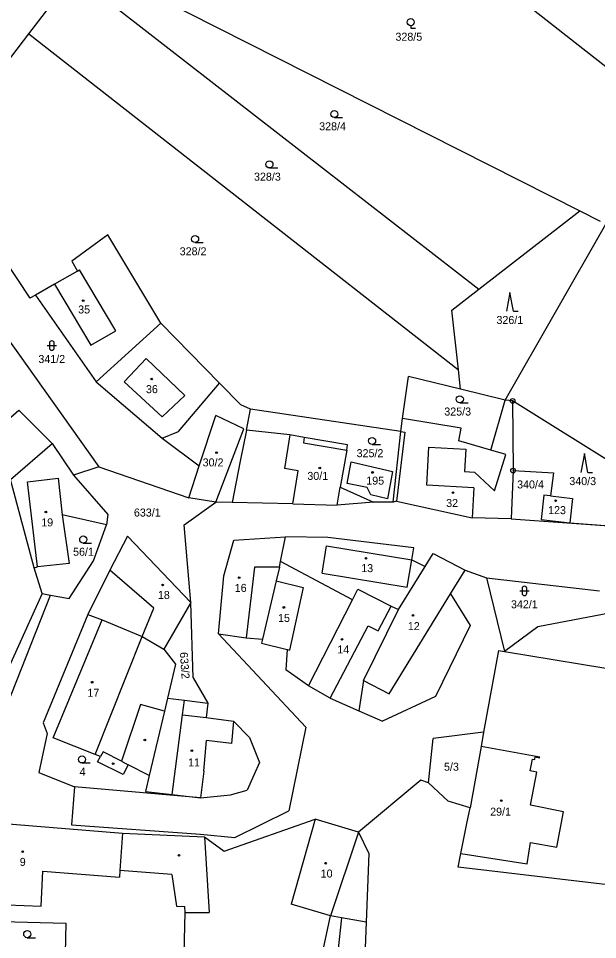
# Model space of a CAD drawing. Extents: x -654459 to -653618, y -1151040 to -1150446.
# Drawn here: x -654025.1 to -653902.1, y -1150881.9 to -1150686.2 of the extents above; entities that cross this region are included whole.
import ezdxf

# ---------------------------------------------------------------- set-up
doc = ezdxf.new("R2010")
doc.units = 0
for name, color, linetype in [('Vrstva 1', 7, 'Continuous'), ('Vrstva 13', 7, 'Continuous'), ('Vrstva 2', 7, 'Continuous'), ('Vrstva 3', 7, 'Continuous'), ('Vrstva 4', 7, 'Continuous'), ('Vrstva 5', 7, 'Continuous'), ('Vrstva 8', 7, 'Continuous')]:
    doc.layers.add(name, color=color, linetype=linetype)

msp = doc.modelspace()

# ---------------------------------------------------------------- linework, layer by layer
at = {"layer": 'Vrstva 1'}
for points in [[(-653968.37, -1150643), (-653888.85, -1150705.43)], [(-654012.68, -1150677.36), (-653927.29, -1150743.71)], [(-654002.02, -1150678.37), (-653905.88, -1150727.07)], [(-654022.86, -1150689.48), (-654015.09, -1150679.29)], [(-654028.99, -1150697.51), (-654022.86, -1150689.48)], [(-654022.86, -1150689.48), (-653931.64, -1150760.87)], [(-654039.87, -1150719.69), (-654022.63, -1150745.66)], [(-653927.29, -1150743.71), (-653905.88, -1150727.07)], [(-653905.88, -1150727.07), (-653901.55, -1150729.27)], [(-653921.68, -1150767.33), (-653900.29, -1150729.91)], [(-654043.19, -1150732.01), (-654008, -1150781.45)], [(-654006.05, -1150732.21), (-654013.73, -1150737.79)], [(-653994.84, -1150750.97), (-654006.05, -1150732.21)], [(-654013.73, -1150737.79), (-654012.53, -1150739.89)], [(-654012.53, -1150739.89), (-654017.42, -1150742.69)], [(-654017.42, -1150742.69), (-654021.44, -1150744.99)], [(-654021.44, -1150744.99), (-654022.63, -1150745.66)], [(-654021.44, -1150744.99), (-654008.57, -1150763.42)], [(-653933.02, -1150748.16), (-653927.29, -1150743.71)], [(-653931.64, -1150760.87), (-653933.02, -1150748.16)], [(-653994.84, -1150750.97), (-654008.57, -1150763.42)], [(-653994.84, -1150750.97), (-653982.37, -1150763.68)], [(-653931.19, -1150764.98), (-653931.64, -1150760.87)], [(-653943.5, -1150771.19), (-653942.2, -1150762.25)], [(-653931.19, -1150764.98), (-653942.2, -1150762.25)], [(-654008.57, -1150763.42), (-653994.51, -1150775.36)], [(-653991.07, -1150773.99), (-653982.37, -1150763.68)], [(-653977.82, -1150768.32), (-653982.37, -1150763.68)], [(-653921.68, -1150767.33), (-653931.19, -1150764.98)], [(-653975.75, -1150769.21), (-653977.82, -1150768.32)], [(-653924.72, -1150777.93), (-653921.68, -1150767.33)], [(-653920.11, -1150767.47), (-653921.68, -1150767.33)], [(-653920.11, -1150767.47), (-653920.01, -1150782.27)], [(-653897.16, -1150781.78), (-653920.11, -1150767.47)], [(-654030.11, -1150773.82), (-654024.99, -1150769.41)], [(-654024.99, -1150769.41), (-654017.92, -1150776.47)], [(-653976.64, -1150773.7), (-653975.75, -1150769.21)], [(-653943.83, -1150773.98), (-653975.75, -1150769.21)], [(-653943.83, -1150773.98), (-653943.5, -1150771.19)], [(-653931.04, -1150773.25), (-653943.5, -1150771.19)], [(-653994.51, -1150775.36), (-653991.07, -1150773.99)], [(-653976.64, -1150773.7), (-653977.95, -1150780.23)], [(-653967.44, -1150774.67), (-653976.64, -1150773.7)], [(-653945.49, -1150788.94), (-653943.83, -1150773.98)], [(-653931.57, -1150775.97), (-653931.04, -1150773.25)], [(-654017.92, -1150776.47), (-654013.38, -1150783.24)], [(-653994.51, -1150775.36), (-653986.65, -1150781.24)], [(-653964.37, -1150775.2), (-653967.44, -1150774.67)], [(-653955.16, -1150776.79), (-653964.37, -1150775.2)], [(-653924.72, -1150777.93), (-653931.57, -1150775.97)], [(-653955.36, -1150777.94), (-653956.75, -1150785.81)], [(-653955.36, -1150777.94), (-653955.16, -1150776.79)], [(-653977.95, -1150780.23), (-653979.71, -1150789.03)], [(-653955.22, -1150785.01), (-653954.42, -1150780.37)], [(-653954.42, -1150780.37), (-653945.61, -1150782.45)], [(-654008, -1150781.45), (-654013.38, -1150783.24)], [(-654008, -1150781.45), (-653988.88, -1150788.06)], [(-653988.88, -1150788.06), (-653986.65, -1150781.24)], [(-653920.01, -1150782.27), (-653920.44, -1150792.48)], [(-653920.01, -1150782.27), (-653911.44, -1150782.73)], [(-654021.7, -1150802.89), (-654026.75, -1150784.17)], [(-654013.38, -1150783.24), (-654006.09, -1150791.56)], [(-653945.61, -1150782.45), (-653946.72, -1150788.28)], [(-653911.44, -1150782.73), (-653912.05, -1150787.64)], [(-653956.75, -1150785.81), (-653949.63, -1150788.96)], [(-653951.03, -1150785.84), (-653955.22, -1150785.01)], [(-653950.24, -1150787.42), (-653951.03, -1150785.84)], [(-653983.13, -1150788.95), (-653988.88, -1150788.06)], [(-653946.72, -1150788.28), (-653950.24, -1150787.42)], [(-653913.46, -1150787.47), (-653914.09, -1150792.62)], [(-653912.05, -1150787.64), (-653913.46, -1150787.47)], [(-653912.05, -1150787.64), (-653907.38, -1150788.2)], [(-653907.38, -1150788.2), (-653907.99, -1150793.34)], [(-653989.9, -1150793.76), (-653983.13, -1150788.95)], [(-653979.71, -1150789.03), (-653983.13, -1150788.95)], [(-653966.77, -1150789.35), (-653979.71, -1150789.03)], [(-653966.77, -1150789.35), (-653957.41, -1150789.58)], [(-653949.63, -1150788.96), (-653957.41, -1150789.58)], [(-653945.49, -1150788.94), (-653949.63, -1150788.96)], [(-653944.79, -1150788.76), (-653945.49, -1150788.94)], [(-653944.79, -1150788.76), (-653928.72, -1150792.32)], [(-654015.79, -1150791.67), (-654014.26, -1150801.98)], [(-654006.36, -1150793.78), (-654015.79, -1150791.67)], [(-654006.09, -1150791.56), (-654006.36, -1150793.78)], [(-654009.12, -1150801.45), (-654006.36, -1150793.78)], [(-653988.45, -1150810.25), (-653989.9, -1150793.76)], [(-653920.44, -1150792.48), (-653928.72, -1150792.32)], [(-653920.44, -1150792.48), (-653896.64, -1150794.22)], [(-653914.09, -1150792.62), (-653907.99, -1150793.34)], [(-653907.99, -1150793.34), (-653896.64, -1150794.22)], [(-654001.87, -1150796.2), (-654005.65, -1150803.38)], [(-654001.87, -1150796.2), (-653988.45, -1150810.25)], [(-653981.47, -1150804.63), (-653979.32, -1150797.04)], [(-653979.32, -1150797.04), (-653968.38, -1150796.31)], [(-653969.41, -1150801.57), (-653968.38, -1150796.31)], [(-653959.35, -1150796.5), (-653968.38, -1150796.31)], [(-653941.12, -1150798.68), (-653959.35, -1150796.5)], [(-653941.54, -1150801.2), (-653941.12, -1150798.68)], [(-653938.7, -1150802.62), (-653937.02, -1150799.89)], [(-653937.02, -1150799.89), (-653930.19, -1150803.4)], [(-654014.26, -1150801.98), (-654021.01, -1150802.74)], [(-654014.26, -1150809.42), (-654009.12, -1150801.45)], [(-653969.64, -1150802.75), (-653969.41, -1150801.57)], [(-653954.1, -1150809.68), (-653969.41, -1150801.57)], [(-653941.54, -1150801.2), (-653938.7, -1150802.62)], [(-654021.7, -1150802.89), (-654021.01, -1150802.74)], [(-654020.03, -1150808.4), (-654021.7, -1150802.89)], [(-654005.65, -1150803.38), (-654010.3, -1150812.82)], [(-653969.64, -1150802.75), (-653970.33, -1150805.68)], [(-653944.35, -1150811.8), (-653938.7, -1150802.62)], [(-653933.29, -1150808.44), (-653930.19, -1150803.4)], [(-653930.19, -1150803.4), (-653925.66, -1150805.07)], [(-653982.57, -1150816.95), (-653981.47, -1150804.63)], [(-653970.33, -1150805.68), (-653973.24, -1150818.04)], [(-653925.66, -1150805.07), (-653921.83, -1150820.7)], [(-653925.66, -1150805.07), (-653901.67, -1150807.82)], [(-653954.1, -1150809.68), (-653952.98, -1150807.48)], [(-653952.98, -1150807.48), (-653945.88, -1150811.03)], [(-654027.56, -1150832.2), (-654018.25, -1150808.73)], [(-654020.03, -1150808.4), (-654027.41, -1150824.64)], [(-654020.03, -1150808.4), (-654018.25, -1150808.73)], [(-654018.25, -1150808.73), (-654014.26, -1150809.42)], [(-653963.48, -1150828.02), (-653954.1, -1150809.68)], [(-653933.29, -1150808.44), (-653929.12, -1150815.14)], [(-653879.89, -1150808.79), (-653914.75, -1150815.43)], [(-653988.45, -1150810.25), (-653994.2, -1150820.22)], [(-653987.95, -1150826.27), (-653988.45, -1150810.25)], [(-653945.88, -1150811.03), (-653944.35, -1150811.8)], [(-654010.3, -1150812.82), (-654019.83, -1150835.82)], [(-654010.3, -1150812.82), (-654007.27, -1150813.93)], [(-653951.82, -1150826.83), (-653944.35, -1150811.8)], [(-654017.66, -1150839.04), (-654007.27, -1150813.93)], [(-654007.27, -1150813.93), (-653998.8, -1150817.5)], [(-653929.12, -1150815.14), (-653936.51, -1150830.25)], [(-653914.75, -1150815.43), (-653921.83, -1150820.7)], [(-653998.8, -1150817.5), (-653994.2, -1150820.22)], [(-653982.57, -1150816.95), (-653964.04, -1150836.77)], [(-653982.57, -1150816.95), (-653976.7, -1150817.82)], [(-653976.7, -1150817.82), (-653973.24, -1150818.04)], [(-653973.24, -1150818.04), (-653973.45, -1150818.92)], [(-653973.45, -1150818.92), (-653968, -1150820.26)], [(-653994.2, -1150820.22), (-653991.71, -1150823.35)], [(-653968, -1150820.26), (-653968.27, -1150824.57)], [(-653923.12, -1150820.49), (-653926.31, -1150837.82)], [(-653923.12, -1150820.49), (-653921.83, -1150820.7)], [(-653921.83, -1150820.7), (-653895.17, -1150825.09)], [(-653991.71, -1150823.35), (-653993.41, -1150830.6)], [(-653963.48, -1150828.02), (-653968.27, -1150824.57)], [(-653987.95, -1150826.27), (-653984.85, -1150831.66)], [(-653951.82, -1150826.83), (-653952.77, -1150833.27)], [(-653958.83, -1150830.58), (-653963.48, -1150828.02)], [(-653993.41, -1150830.6), (-653994.05, -1150833.34)], [(-653993.41, -1150830.6), (-653989.83, -1150831.04)], [(-653989.83, -1150831.04), (-653984.85, -1150831.66)], [(-653958.83, -1150830.58), (-653952.77, -1150833.27)], [(-653936.51, -1150830.25), (-653947.77, -1150835.5)], [(-653984.85, -1150831.66), (-653985.2, -1150834.68)], [(-653952.77, -1150833.27), (-653947.77, -1150835.5)], [(-653994.05, -1150833.34), (-653997.27, -1150847.01)], [(-653985.2, -1150834.68), (-653979.39, -1150835.48)], [(-654019.83, -1150835.82), (-654018.93, -1150838.08)], [(-653979.39, -1150835.48), (-653975.96, -1150838.93)], [(-653964.04, -1150836.77), (-653967.66, -1150854.52)], [(-654018.93, -1150838.08), (-654020.7, -1150846.4)], [(-654008.75, -1150842.55), (-654017.66, -1150839.04)], [(-653975.96, -1150838.93), (-653973.87, -1150844.24)], [(-653937.98, -1150848.62), (-653936.97, -1150839.17)], [(-653926.31, -1150837.82), (-653936.97, -1150839.17)], [(-653926.31, -1150837.82), (-653926.8, -1150840.86)], [(-653931.11, -1150863.57), (-653917.05, -1150865.8), (-653916.33, -1150861.24), (-653910.76, -1150862.28), (-653909.31, -1150854.72), (-653916.33, -1150853.37), (-653914.96, -1150846.3), (-653916.39, -1150846.02), (-653915.92, -1150843.57), (-653915.42, -1150843.66), (-653915.31, -1150843.07), (-653914.38, -1150843.25), (-653914.35, -1150843.11), (-653926.8, -1150840.86)], [(-653926.8, -1150840.86), (-653929.15, -1150853.89)], [(-654007.63, -1150842.99), (-654008.75, -1150842.55)], [(-654008.24, -1150844.1), (-654007.63, -1150842.99)], [(-654002.79, -1150846.83), (-654008.24, -1150844.1)], [(-654001.75, -1150844.76), (-654002.79, -1150846.83)], [(-653997.27, -1150847.01), (-654001.75, -1150844.76)], [(-653973.87, -1150844.24), (-653975.07, -1150846.96)], [(-654020.7, -1150846.4), (-654013.17, -1150849.43)], [(-653997.27, -1150847.01), (-653998.07, -1150850.41)], [(-653975.07, -1150846.96), (-653976.47, -1150850.13)], [(-653939.58, -1150848.05), (-653952.85, -1150859.1)], [(-653937.98, -1150848.62), (-653939.58, -1150848.05)], [(-653933.78, -1150852.52), (-653937.98, -1150848.62)], [(-654013.17, -1150849.43), (-654013.81, -1150857.53)], [(-653986.41, -1150851.81), (-654013.17, -1150849.43)], [(-653998.07, -1150850.41), (-653992.43, -1150851.08)], [(-653980, -1150851.16), (-653976.47, -1150850.13)], [(-653992.43, -1150851.08), (-653986.41, -1150851.81)], [(-653986.41, -1150851.81), (-653980, -1150851.16)], [(-653929.15, -1150853.89), (-653933.78, -1150852.52)], [(-653979.12, -1150860.22), (-653967.66, -1150854.52)], [(-653929.82, -1150857.2), (-653929.15, -1150853.89)], [(-653981.39, -1150863.1), (-653962.07, -1150856.32)], [(-653952.85, -1150859.1), (-653962.07, -1150856.32)], [(-654029.83, -1150857.12), (-654002.97, -1150859.28)], [(-654013.81, -1150857.53), (-653986.42, -1150859.51)], [(-653931.11, -1150863.57), (-653929.82, -1150857.2)], [(-654002.97, -1150859.28), (-653985.52, -1150860.06)], [(-653986.42, -1150859.51), (-653979.12, -1150860.22)], [(-653985.52, -1150860.06), (-653981.39, -1150863.1)], [(-653985.52, -1150860.06), (-653984.54, -1150876.12)], [(-653952.85, -1150859.1), (-653950.63, -1150863.63)], [(-653950.63, -1150863.63), (-653951.19, -1150878.22)], [(-653931.71, -1150866.51), (-653931.11, -1150863.57)], [(-653879.52, -1150872.65), (-653931.71, -1150866.51)], [(-653989.92, -1150887.76), (-653989.66, -1150876.12)], [(-653989.66, -1150876.12), (-653984.54, -1150876.12)], [(-654031.34, -1150877.98), (-654015, -1150878.38)], [(-653960.43, -1150884.41), (-653958.81, -1150876.82)], [(-653956.45, -1150877.25), (-653958.81, -1150876.82)], [(-653951.19, -1150878.22), (-653956.45, -1150877.25)], [(-653951.19, -1150878.22), (-653951.68, -1150890.98)], [(-654015, -1150878.38), (-654015.19, -1150887.93)]]:
    msp.add_lwpolyline(points, dxfattribs=at)
at = {"layer": 'Vrstva 3'}
for p, q in [((-653941.76, -1150687.74), (-653941.76, -1150688.24)), ((-653941.76, -1150688.24), (-653940.76, -1150688.24)), ((-653957.99, -1150707.27), (-653956.24, -1150707.27)), ((-653971.76, -1150717.97), (-653970.01, -1150717.97)), ((-653987.55, -1150733.82), (-653985.8, -1150733.82)), ((-653920.69, -1150744.41), (-653921.44, -1150748.41)), ((-653919.94, -1150748.41), (-653920.69, -1150744.41)), ((-653919.94, -1150748.41), (-653918.94, -1150748.41)), ((-654018.97, -1150755.7), (-654016.97, -1150755.7)), ((-654018.47, -1150755.2), (-654018.47, -1150756.2)), ((-654017.47, -1150756.2), (-654017.47, -1150755.2)), ((-653931.33, -1150767.86), (-653929.58, -1150767.86)), ((-653949.96, -1150776.71), (-653948.21, -1150776.71)), ((-653904.87, -1150778.64), (-653905.62, -1150782.64)), ((-653904.12, -1150782.64), (-653904.87, -1150778.64)), ((-653904.12, -1150782.64), (-653903.12, -1150782.64)), ((-654011.3, -1150797.65), (-654009.55, -1150797.65)), ((-653918.61, -1150807.81), (-653916.61, -1150807.81)), ((-653918.11, -1150807.31), (-653918.11, -1150808.31)), ((-653917.11, -1150808.31), (-653917.11, -1150807.31)), ((-654011.56, -1150844.37), (-654009.81, -1150844.37)), ((-654023.2, -1150881.49), (-654021.45, -1150881.49))]:
    msp.add_line(p, q, dxfattribs=at)
for centre in [(-653941.76, -1150686.99), (-653957.99, -1150706.52), (-653971.76, -1150717.22), (-653987.55, -1150733.07), (-653931.33, -1150767.11), (-653949.96, -1150775.96), (-654011.3, -1150796.9), (-654011.56, -1150843.62), (-654023.2, -1150880.74)]:
    msp.add_circle(centre, 0.75, dxfattribs=at)
for centre, start, end in [((-654017.97, -1150755.2), 0, 180), ((-654017.97, -1150756.2), 180, 359.9879), ((-653917.61, -1150807.31), 0, 180), ((-653917.61, -1150808.31), 180, 359.9879)]:
    msp.add_arc(centre, 0.5, start, end, dxfattribs=at)
at = {"layer": 'Vrstva 4'}
for points in [[(-654012.53, -1150739.89), (-654012.09, -1150739.64)], [(-654004.4, -1150752.58), (-654012.09, -1150739.64)], [(-654017.42, -1150742.69), (-654009.71, -1150755.59)], [(-654009.71, -1150755.59), (-654004.4, -1150752.58)], [(-654002.62, -1150763.37), (-653997.97, -1150758.48)], [(-653997.97, -1150758.48), (-653989.74, -1150766.3)], [(-654002.62, -1150763.37), (-653994.55, -1150770.82)], [(-653994.55, -1150770.82), (-653989.74, -1150766.3)], [(-653986.65, -1150781.24), (-653983.17, -1150770.58)], [(-653977.23, -1150773.42), (-653983.17, -1150770.58)], [(-653983.13, -1150788.95), (-653977.23, -1150773.42)], [(-653943.01, -1150774.12), (-653944.79, -1150788.76)], [(-653943.83, -1150773.98), (-653943.01, -1150774.12)], [(-654026.75, -1150784.17), (-654017.92, -1150776.47)], [(-653967.44, -1150774.67), (-653968.56, -1150781.8)], [(-653964.37, -1150775.2), (-653964.56, -1150776.33)], [(-653964.56, -1150776.33), (-653955.36, -1150777.94)], [(-653938.36, -1150785.35), (-653937.92, -1150777.3)], [(-653937.92, -1150777.3), (-653930.07, -1150777.72)], [(-653930.07, -1150777.72), (-653930.33, -1150782.47)], [(-653921.53, -1150778.85), (-653924.72, -1150777.93)], [(-653923.96, -1150786.59), (-653921.53, -1150778.85)], [(-653965.66, -1150782.34), (-653968.56, -1150781.8)], [(-653966.77, -1150789.35), (-653965.66, -1150782.34)], [(-654023.17, -1150784.65), (-654016.61, -1150783.86)], [(-654016.61, -1150783.86), (-654015.79, -1150791.67)], [(-653930.33, -1150782.47), (-653928.2, -1150782.59)], [(-653928.2, -1150782.59), (-653923.96, -1150786.59)], [(-654021.01, -1150802.74), (-654023.17, -1150784.65)], [(-653957.41, -1150789.58), (-653956.75, -1150785.81)], [(-653928.38, -1150785.89), (-653938.36, -1150785.35)], [(-653928.38, -1150785.89), (-653928.72, -1150792.32)], [(-653960.58, -1150804.07), (-653959.64, -1150798.27)], [(-653959.64, -1150798.27), (-653941.54, -1150801.2)], [(-653942.48, -1150807), (-653941.54, -1150801.2)], [(-653996.3, -1150811.5), (-654005.65, -1150803.38)], [(-653974.91, -1150802.8), (-653976.7, -1150817.82)], [(-653969.64, -1150802.75), (-653974.91, -1150802.8)], [(-653970.33, -1150805.68), (-653964.57, -1150807.1)], [(-653960.58, -1150804.07), (-653942.48, -1150807)], [(-653964.57, -1150807.1), (-653967.51, -1150820.38)], [(-653946.35, -1150829.66), (-653933.29, -1150808.44)], [(-653998.8, -1150817.5), (-653996.3, -1150811.5)], [(-653948.65, -1150816.31), (-653945.88, -1150811.03)], [(-653958.83, -1150830.58), (-653950.77, -1150815.25)], [(-653950.77, -1150815.25), (-653948.65, -1150816.31)], [(-654008.75, -1150842.55), (-653998.8, -1150817.5)], [(-653968, -1150820.26), (-653967.51, -1150820.38)], [(-653951.82, -1150826.83), (-653946.35, -1150829.66)], [(-653990.23, -1150834.13), (-653989.83, -1150831.04)], [(-653999.17, -1150831.96), (-654003.16, -1150843.99)], [(-653994.05, -1150833.34), (-653999.17, -1150831.96)], [(-653992.43, -1150851.08), (-653990.23, -1150834.13)], [(-653990.23, -1150834.13), (-653985.2, -1150834.68)], [(-653979.39, -1150835.48), (-653979.84, -1150840.23)], [(-653985.69, -1150846.08), (-653985.11, -1150839.63)], [(-653979.84, -1150840.23), (-653985.11, -1150839.63)], [(-654007.08, -1150841.98), (-654007.63, -1150842.99)], [(-654003.16, -1150843.99), (-654007.08, -1150841.98)], [(-654003.16, -1150843.99), (-654001.75, -1150844.76)], [(-653985.69, -1150846.08), (-653986.41, -1150851.81)], [(-653962.07, -1150856.32), (-653967.15, -1150874.34)], [(-654002.97, -1150859.28), (-654003.53, -1150867.19)], [(-653952.85, -1150859.1), (-653958.81, -1150876.82)], [(-654020.25, -1150874.82), (-654019.86, -1150867.33)], [(-654019.86, -1150867.33), (-654003.63, -1150868.6)], [(-654003.53, -1150867.19), (-654003.63, -1150868.6)], [(-653992.49, -1150868.1), (-654003.53, -1150867.19)], [(-653992.49, -1150868.1), (-653991.53, -1150874.8)], [(-654031.11, -1150874.37), (-654020.25, -1150874.82)], [(-653958.81, -1150876.82), (-653967.15, -1150874.34)], [(-653991.53, -1150874.8), (-653989.71, -1150874.83)], [(-653989.66, -1150876.12), (-653989.71, -1150874.83)], [(-653956.45, -1150877.25), (-653958.03, -1150891.72)]]:
    msp.add_lwpolyline(points, dxfattribs=at)
at = {"layer": 'Vrstva 5'}
for centre in [(-654011.3, -1150746.15), (-653996.77, -1150762.81), (-653983, -1150778.46), (-653961.07, -1150781.71), (-653949.87, -1150782.66), (-653932.79, -1150786.94), (-653910.99, -1150788.66), (-654019.24, -1150791.07), (-653951.24, -1150800.89), (-653978.19, -1150805), (-653994.45, -1150806.56), (-653968.7, -1150811.33), (-653941.28, -1150813.04), (-653956.36, -1150818.12), (-654009.42, -1150827.21), (-653998.21, -1150839.48), (-653988.23, -1150841.75), (-654004.93, -1150844.53), (-653922.53, -1150852.38), (-654024.16, -1150863.2), (-653990.95, -1150863.99), (-653959.81, -1150865.67)]:
    msp.add_circle(centre, 0.175, dxfattribs=at)
at = {"layer": 'Vrstva 8'}
for centre, radius in [((-653920.11, -1150767.47), 0.5), ((-653920.11, -1150767.47), 0.0303), ((-653920.01, -1150782.27), 0.5), ((-653920.01, -1150782.27), 0.0303)]:
    msp.add_circle(centre, radius, dxfattribs=at)

# ---------------------------------------------------------------- texts
at = {"layer": 'Vrstva 13'}
for s, p in [('35', (-654012.38, -1150748.88)), ('36', (-653997.98, -1150765.81)), ('30/2', (-653985.94, -1150781.37)), ('30/1', (-653963.71, -1150784.24)), ('195', (-653951.2, -1150785.25)), ('32', (-653934.23, -1150789.99)), ('123', (-653912.59, -1150791.51)), ('19', (-654020.22, -1150794.11)), ('13', (-653952.27, -1150803.83)), ('18', (-653995.45, -1150809.53)), ('16', (-653979.13, -1150808.03)), ('15', (-653969.93, -1150814.41)), ('12', (-653942.37, -1150816.15)), ('14', (-653957.35, -1150821.11)), ('17', (-654010.42, -1150830.31)), ('11', (-653989.03, -1150845.1)), ('29/1', (-653924.89, -1150855.57)), ('9', (-654024.78, -1150866.24)), ('10', (-653960.88, -1150868.71))]:
    msp.add_text(s, height=1.7, dxfattribs=at).set_placement(p)
at = {"layer": 'Vrstva 2'}
for s, p in [('328/5', (-653945, -1150690.94)), ('328/4', (-653961.2, -1150709.97)), ('328/3', (-653975.04, -1150720.67)), ('328/2', (-653990.82, -1150736.52)), ('326/1', (-653923.55, -1150751.11)), ('341/2', (-654020.83, -1150759.4)), ('325/3', (-653934.63, -1150770.56)), ('325/2', (-653953.25, -1150779.41)), ('340/4', (-653919.17, -1150786.05)), ('340/3', (-653908.08, -1150785.34)), ('633/1', (-654000.54, -1150792.02)), ('56/1', (-654013.46, -1150800.35)), ('342/1', (-653920.47, -1150811.51)), ('5/3', (-653934.69, -1150846.02)), ('4', (-654012.08, -1150847.07))]:
    msp.add_text(s, height=1.7, dxfattribs=at).set_placement(p)
msp.add_text('633/2', height=1.7, rotation=274.1849, dxfattribs=at).set_placement((-653990.8, -1150820.88))

doc.saveas('drawing.dxf')
